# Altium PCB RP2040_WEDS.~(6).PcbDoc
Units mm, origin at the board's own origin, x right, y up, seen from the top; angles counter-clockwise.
Board outline 55 x 66 mm, 2 copper layers (F.Cu, B.Cu); 69 components, 40 nets, 258 pads, 71 vias.
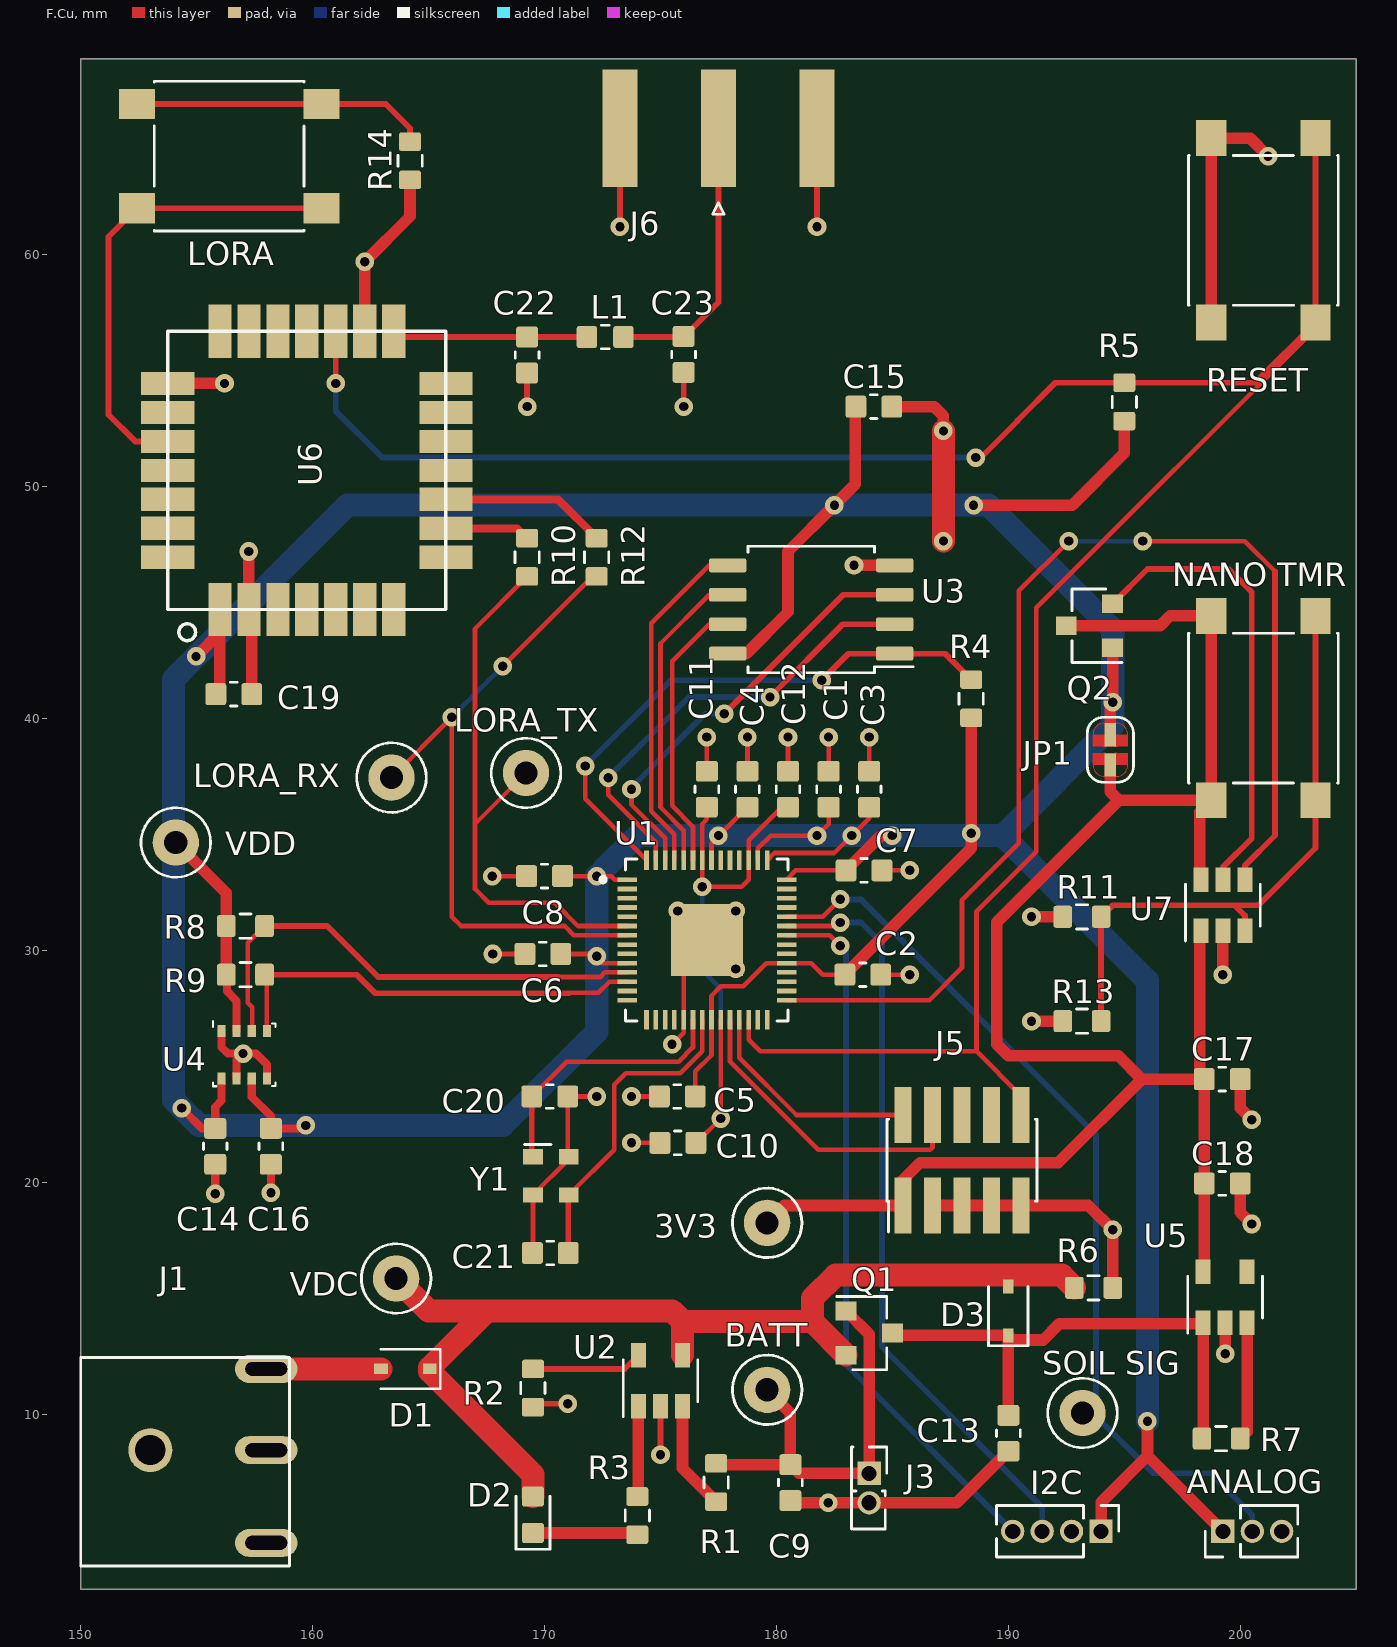
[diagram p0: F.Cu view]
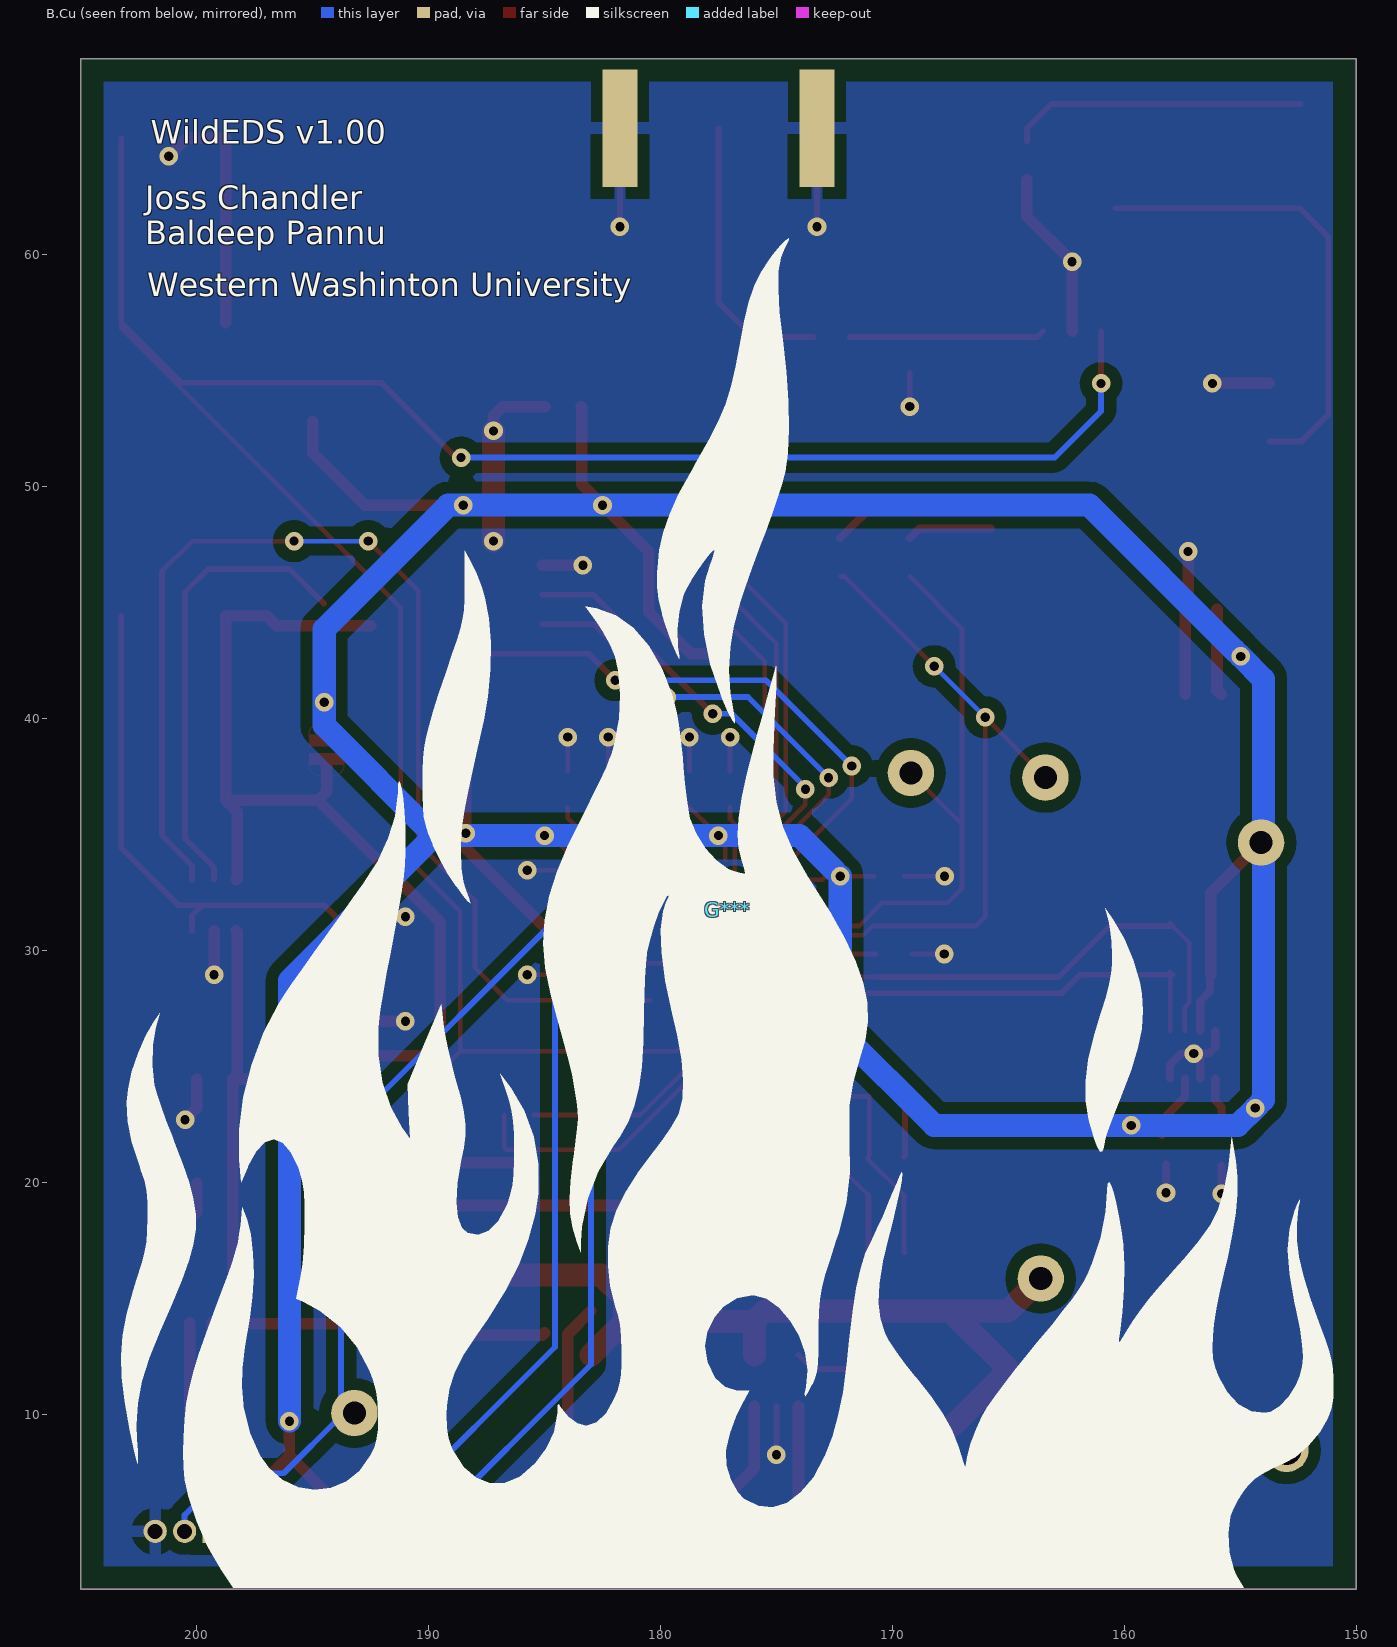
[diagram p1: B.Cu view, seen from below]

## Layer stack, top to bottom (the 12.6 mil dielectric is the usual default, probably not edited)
F.Mask: solder mask 0.0102, Solder Resist, Dk 3.5
F.Cu: signal copper 0.0356
Dielectric 1: dielectric 0.32, FR-4, Dk 4.8
B.Cu: signal copper 0.0356
B.Mask: solder mask 0.0102, Solder Resist, Dk 3.5

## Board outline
205,68.45 205,2.45 150,2.45 150,68.45 205,68.45

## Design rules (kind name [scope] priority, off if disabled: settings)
Clearance "Clearence 0.508_Polygon" [InNamedPolygon('B.Cu-GND')] p1: gap=0.508 ignorepadtopadclearanceinfootprint=FALSE
Clearance "Clearence 0.2_NetClass" [InNetClass('Default')] p2: gap=0.2 ignorepadtopadclearanceinfootprint=FALSE
HoleSize "Hole Size (Default)" [All] p1: absolutevalues=TRUE maxlimit=10 minlimit=0.3 maxpercent=80.000 minpercent=20.000
MinimumSolderMaskSliver [All] p1: minsoldermaskwidth=0
PolygonConnect Polygon_B.Cu-GND_ConnectDirect [IsNamedPolygon('B.Cu-GND') vs IsVia] p1: connectstyle=Direct reliefconductorwidth=0.254 reliefentries=4 polygonreliefangle="90 Angle" airgapwidth=0.254
PolygonConnect Polygon_B.Cu-GND_ConnectRelief45 [IsNamedPolygon('B.Cu-GND') vs (IsThruPin or IsSMTPin) and (PadShape_AllLayers = 'Round')] p2: connectstyle=Relief reliefconductorwidth=0.508 reliefentries=4 polygonreliefangle="45 Angle" airgapwidth=0.508
PolygonConnect Polygon_B.Cu-GND_ConnectRelief90 [IsNamedPolygon('B.Cu-GND') vs (IsThruPin or IsSMTPin) and (PadShape_AllLayers <> 'Round')] p3: connectstyle=Relief reliefconductorwidth=0.508 reliefentries=4 polygonreliefangle="90 Angle" airgapwidth=0.508
RoutingVias [All] p1: holewidth=0.711 width=1.27 viastyle="Through Hole" minholewidth=0.711 minwidth=1.27 maxholewidth=0.711 maxwidth=1.27
SilkToSilkClearance [All] p1: silktosilkclearance=0
SilkToSolderMaskClearance [IsPad] p1: minsilkscreentomaskgap=0 clearancetoexposedcopper=TRUE
SolderMaskExpansion [All] p1: expansion=0.102 istentingtop=FALSE
Width [All] p1: maxlimit=10 minlimit=0.2 preferedwidth=0.25 minimp=50.000000 maximp=50.000000 favimp=50.000000
26 further rules are at their usual default settings.

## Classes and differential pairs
net class Default: +1V1 +3V3 +BATT DONE GND LORA_RX LORA_TX Net-(C13-Pad1) Net-(C22-Pad1) Net-(C23-Pad1) Net-(D1-Pad2) Net-(D2-Pad1) Net-(Q2-Pad2) Net-(R1-Pad2) Net-(R2-Pad2) Net-(R3-Pad2) Net-(R7-Pad1) Net-(R10-Pad1) Net-(R11-Pad2) Net-(R12-Pad1) Net-(R14-Pad2) Net-(SW3-Pad1) QSPI_CLK QSPI_CSN QSPI_SD0 QSPI_SD1 QSPI_SD2 QSPI_SD3 RESET SCL SCL_SOIL SDA SDA_SOIL SOIL_SIG SWD_CLK SWD_DIO VDC VDD XIN XOUT

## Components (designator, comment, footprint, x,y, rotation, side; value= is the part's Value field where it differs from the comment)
3V3 "TestPoint" TestPoint_Loop_D1.80mm_Drill1.0mm_Beaded 179.6,18.25 r0 top
ANALOG "Conn_01x03_Male" PinHeader_1x03_P1.27mm_Vertical 199.25,4.95 r90 top
BATT "TestPoint" TestPoint_Loop_D1.80mm_Drill1.0mm_Beaded 179.6,11.05 r0 top
C1 "1uF" C_0603_1608Metric 182.25,36.95 r90 top
C2 "100nF" C_0603_1608Metric 183.725,28.95 r0 top
C3 "100nF" C_0603_1608Metric 184,36.95 r90 top
C4 "100nF" C_0603_1608Metric 178.75,36.95 r90 top
C5 "100nF" C_0603_1608Metric 175.725,23.7 r180 top
C6 "100nF" C_0603_1608Metric 169.926,29.845 r180 top
C7 "100nF" C_0603_1608Metric 183.775,33.45 r0 top
C8 "100nF" C_0603_1608Metric 170,33.2 r180 top
C9 "10uF" C_0603_1608Metric 180.6,7.05 r270 top
C10 "100nF" C_0603_1608Metric 175.75,21.7 r180 top
C11 "100nF" C_0603_1608Metric 177,36.95 r90 top
C12 "1uF" C_0603_1608Metric 180.5,36.95 r90 top
C13 "10uF" C_0603_1608Metric 190,9.175 r270 top
C14 "100nF" C_0603_1608Metric 155.8,21.55 r270 top
C15 "C" C_0603_1608Metric 184.2,53.45 r0 top
C16 "100nF" C_0603_1608Metric 158.2,21.55 r270 top
C17 "10uF" C_0603_1608Metric 199.225,24.45 r0 top
C18 "10uF" C_0603_1608Metric 199.225,19.95 r0 top
C19 "4.7uF" C_0603_1608Metric 156.6,41.05 r0 top
C20 "8pF" C_0603_1608Metric 170.225,23.7 r0 top
C21 "8pF" C_0603_1608Metric 170.25,16.95 r0 top
C22 "DNP" C_0603_1608Metric 169.25,55.675 r270 top
C23 "DNP" C_0603_1608Metric 176,55.7 r270 top
D1 "D_Schottky" D_SOD-323 164,11.95 r180 top
D2 "LED" LED_0603_1608Metric 169.5,5.663 r90 top
D3 "D_Schottky" D_SOD-323 190,14.45 r90 top
G*** "LOGO" Flame_Logo 177.1,31.75 r0 bottom
I2C "Conn_01x04_Male" PinHeader_1x04_P1.27mm_Vertical 194,4.95 r270 top
J1 "Barrel_Jack_Switch_Pin3Ring" 54-00125 154,13.45 r0 top
J3 "LiPo Batt" PinHeader_2x01_P1.27mm_Vertical 184,7.45 r270 top
J5 "Conn_02x05_Odd_Even" PinHeader_2x05_P1.27mm_Vertical_SMD 188,20.95 r90 top
J6 "SMA-J-P-H-RA-TH1" SMA_Amphenol_132289_EdgeMount_new 177.5,65.45 r90 top
JP1 "SolderJumper_2_Open" SolderJumper-2_P1.3mm_Open_RoundedPad1.0x1.5mm 194.4,38.65 r90 top
L1 "0H" L_0603_1608Metric 172.612,56.45 r0 top
LORA "SW_Push" SW_Push_1P1T_NO_6x6mm_H9.5mm 156.4,64.25 r180 top
LORA_RX "TestPoint" TestPoint_Loop_D1.80mm_Drill1.0mm_Beaded 163.4,37.45 r0 top
LORA_TX "TestPoint" TestPoint_Loop_D1.80mm_Drill1.0mm_Beaded 169.2,37.65 r0 top
"NANO TMR" "SW_Push" SW_Push_1P1T_NO_6x6mm_H9.5mm 201,40.45 r270 top
Q1 "Q_PMOS_DGS" SOT-23 184,13.5 r0 top
Q2 "Q_PMOS_DGS" SOT-23 193.5,44 r180 top
R1 "0" R_0603_1608Metric 177.4,7.05 r270 top
R2 "2k" R_0603_1608Metric 169.5,11.125 r90 top
R3 "10k" R_0603_1608Metric 174,5.625 r90 top
R4 "10k" R_0603_1608Metric 188.4,40.85 r270 top
R5 "10k" R_0603_1608Metric 195,53.65 r90 top
R6 "10k" R_0603_1608Metric 193.675,15.45 r0 top
R7 "10k" R_0603_1608Metric 199.175,8.95 r180 top
R8 "10k" R_0603_1608Metric 157.1,31.05 r0 top
R9 "10k" R_0603_1608Metric 157.1,28.95 r0 top
R10 "22" R_0603_1608Metric 169.25,46.95 r270 top
R11 "221k" R_0603_1608Metric 193.175,31.45 r0 top
R12 "22" R_0603_1608Metric 172.25,46.95 r270 top
R13 "287k" R_0603_1608Metric 193.175,26.95 r0 top
R14 "470" R_0603_1608Metric 164.2,64.05 r90 top
RESET "SW_Push" SW_Push_1P1T_NO_6x6mm_H9.5mm 201,61.05 r270 top
"SOIL SIG" "TestPoint" TestPoint_Loop_D1.80mm_Drill1.0mm_Beaded 193.2,10.05 r0 top
U1 "RP2040" QFN40P700X700X90-57N 177,30.45 r0 top
U2 "MCP73831-2-OT" SOT-23-5 175,11.45 r90 top
U3 "W25Q128JVS" SOIC-8_5.23x5.23mm_P1.27mm 181.5,44.7 r180 top
U4 "BME280" Bosch_LGA-8_2.5x2.5mm_P0.65mm_ClockwisePinNumbering 157.05,25.5 r0 top
U5 "AP2112K-3.3" SOT-23-5 199.35,15.05 r90 top
U6 "LoRa-E5" LoRa-E5 159.75,50.7 r90 top
U7 "TPL5110" SOT-23-6 199.25,31.95 r90 top
VDC "TestPoint" TestPoint_Loop_D1.80mm_Drill1.0mm_Beaded 163.6,15.85 r0 top
VDD "TestPoint" TestPoint_Loop_D1.80mm_Drill1.0mm_Beaded 154.1,34.65 r0 top
Y1 "Crystal_GND24" Oscillator_SMD_Abracon_ASDMB-4Pin_2.5x2.0mm 170.275,20.275 r270 top

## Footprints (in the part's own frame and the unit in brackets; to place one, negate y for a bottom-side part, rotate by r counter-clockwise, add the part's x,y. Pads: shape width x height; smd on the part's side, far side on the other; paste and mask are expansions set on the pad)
54-00125 [mm]
  rrect100% 2.7x1.2 hole 0.6 slot 1.8 at 0 deg paste-2.7 mask+0.051: 1(4,-1.5) 2(4,-5) 3(4,-9)
  round 1.9 hole 1.3 paste-1.9 mask+0.051: Un1(-1,-5)
  silkscreen extent -4,-10 5,-1
Bosch_LGA-8_2.5x2.5mm_P0.65mm_ClockwisePinNumbering [mm]
  rect 0.35x0.5 smd mask+0.051: 1(-0.975,1.025) 2(-0.325,1.025) 3(0.325,1.025) 4(0.975,1.025) 5(0.975,-1.025) 6(0.325,-1.025) 7(-0.325,-1.025) 8(-0.975,-1.025)
  silkscreen extent -1.35,-1.36 1.35,1.45
C_0603_1608Metric [mm]
  rrect25% 0.9x0.95 smd mask+0.051: 1(-0.775,0) 2(0.775,0)
  silkscreen extent -0.14,-0.51 0.14,0.51
D_SOD-323 [mm]
  rect 0.6x0.45 smd mask+0.051: 1(-1.05,0) 2(1.05,0)
  silkscreen extent -1.5,-0.85 1.05,0.85
Flame_Logo [mm]
  silkscreen extent -26.12,-28.96 26.16,29.24
L_0603_1608Metric [mm]
  rrect25% 0.875x0.95 smd mask+0.051: 1(-0.787,0) 2(0.787,0)
  silkscreen extent -0.16,-0.51 0.16,0.51
LED_0603_1608Metric [mm]
  rrect25% 0.875x0.95 smd mask+0.051: 1(-0.787,0) 2(0.787,0)
  silkscreen extent -1.49,-0.73 0.8,0.73
LoRa-E5 [mm]
  rect 2.3x1 smd mask+0.051: 1(-6,3.75) 2(-6,2.5) 3(-6,1.25) 4(-6,0) 5(-6,-1.25) 6(-6,-2.5) 7(-6,-3.75) 15(6,-3.75) 16(6,-2.5) 17(6,-1.25) 18(6,0) 19(6,1.25) 20(6,2.5) 21(6,3.75)
  rect 1x2.3 smd mask+0.051: 8(-3.75,-6) 9(-2.5,-6) 10(-1.25,-6) 11(0,-6) 12(1.25,-6) 13(2.5,-6) 14(3.75,-6) 22(3.75,6) 23(2.5,6) 24(1.25,6) 25(0,6) 26(-1.25,6) 27(-2.5,6) 28(-3.75,6)
  silkscreen extent -7.34,-6 6,6
Oscillator_SMD_Abracon_ASDMB-4Pin_2.5x2.0mm [mm]
  rect 0.65x0.85 smd mask+0.051: 1(-0.825,-0.775) 2(0.825,-0.775) 3(0.825,0.775) 4(-0.825,0.775)
  silkscreen extent -1.35,-1.14 -1.35,0
PinHeader_1x03_P1.27mm_Vertical [mm]
  rect 1x1 hole 0.65 paste-1 mask+0.051: 1(0,0)
  rrect100% 1x1 hole 0.65 paste-1 mask+0.051: 2(0,-1.27) 3(0,-2.54)
  silkscreen extent -1.11,-3.23 1.11,0.76
PinHeader_1x04_P1.27mm_Vertical [mm]
  rect 1x1 hole 0.65 paste-1 mask+0.051: 1(0,0)
  rrect100% 1x1 hole 0.65 paste-1 mask+0.051: 2(0,-1.27) 3(0,-2.54) 4(0,-3.81)
  silkscreen extent -1.11,-4.5 1.11,0.76
PinHeader_2x01_P1.27mm_Vertical [mm]
  rect 1x1 hole 0.65 paste-1 mask+0.051: 1(0,0)
  rrect100% 1x1 hole 0.65 paste-1 mask+0.051: 2(1.27,0)
  silkscreen extent -1.13,-0.76 2.4,0.76
PinHeader_2x05_P1.27mm_Vertical_SMD [mm]
  rect 2.4x0.74 smd mask+0.051: 1(-1.95,2.54) 2(1.95,2.54) 3(-1.95,1.27) 4(1.95,1.27) 5(-1.95,0) 6(1.95,0) 7(-1.95,-1.27) 8(1.95,-1.27) 9(-1.95,-2.54) 10(1.95,-2.54)
  silkscreen extent -3.09,-3.23 1.77,3.23
QFN40P700X700X90-57N [mm]
  rrect3% 0.84x0.2 smd mask+0.051: 1(-3.435,2.6) 2(-3.435,2.2) 3(-3.435,1.8) 4(-3.435,1.4) 5(-3.435,1) 6(-3.435,0.6) 7(-3.435,0.2) 8(-3.435,-0.2) 9(-3.435,-0.6) 10(-3.435,-1) 11(-3.435,-1.4) 12(-3.435,-1.8) 13(-3.435,-2.2) 14(-3.435,-2.6) 29(3.435,-2.6) 30(3.435,-2.2) 31(3.435,-1.8) 32(3.435,-1.4) 33(3.435,-1) 34(3.435,-0.6) 35(3.435,-0.2) 36(3.435,0.2) 37(3.435,0.6) 38(3.435,1) 39(3.435,1.4) 40(3.435,1.8) 41(3.435,2.2) 42(3.435,2.6)
  rrect10% 0.2x0.84 smd mask+0.051: 15(-2.6,-3.435) 16(-2.2,-3.435) 17(-1.8,-3.435) 18(-1.4,-3.435) 19(-1,-3.435) 20(-0.6,-3.435) 21(-0.2,-3.435) 22(0.2,-3.435) 23(0.6,-3.435) 24(1,-3.435) 25(1.4,-3.435) 26(1.8,-3.435) 27(2.2,-3.435) 28(2.6,-3.435) 43(2.6,3.435) 44(2.2,3.435) 45(1.8,3.435) 46(1.4,3.435) 47(1,3.435) 48(0.6,3.435) 49(0.2,3.435) 50(-0.2,3.435) 51(-0.6,3.435) 52(-1,3.435) 53(-1.4,3.435) 54(-1.8,3.435) 55(-2.2,3.435) 56(-2.6,3.435)
  rect 3.1x3.1 smd paste-3.1 mask+0.051: 57(0,0)
  silkscreen extent -4.57,-3.5 3.5,3.5
R_0603_1608Metric [mm]
  rrect25% 0.8x0.95 smd mask+0.051: 1(-0.825,0) 2(0.825,0)
  silkscreen extent -0.24,-0.52 0.24,0.52
SMA_Amphenol_132289_EdgeMount_new [mm]
  rect 5.08x1.5 smd mask+0.051: 1(0,0) 2(0,-4.25) 3(0,4.25)
  rect 5.08x1.5 smd far side mask+0.051: 4(0,4.25) 5(0,-4.25)
  silkscreen extent -3.71,-0.25 -3.21,0.25
SOIC-8_5.23x5.23mm_P1.27mm [mm]
  rrect25% 1.6x0.6 smd mask+0.051: 1(-3.6,1.905) 2(-3.6,0.635) 3(-3.6,-0.635) 4(-3.6,-1.905) 5(3.6,-1.905) 6(3.6,-0.635) 7(3.6,0.635) 8(3.6,1.905)
  silkscreen extent -4.4,-2.73 2.73,2.73
SolderJumper-2_P1.3mm_Open_RoundedPad1.0x1.5mm [mm]
  rect 1x0.5 smd paste-1 mask+0.051: 1(-0.65,0) 2(0.65,0)
  F.Cu circle w0: c-0.65,0.25 r0.5
  F.Cu circle w0: c-0.65,-0.25 r0.5
  F.Cu region: -0.15,-0.75 -0.65,-0.75 -0.65,0.75 -0.15,0.75
  F.Cu region: 0.65,-0.75 0.15,-0.75 0.15,0.75 0.65,0.75
  F.Cu lines w0: 0.217,0 ccw(c0.65,-0.25) 0.65,-0.75 ccw(c0.65,-0.25) 1.083,0 ; 0.217,0 cw(c0.65,-0.25) 1.083,0 ; 0.217,0 ccw(c0.65,0.25) 0.65,-0.25 ccw(c0.65,0.25) 1.083,0 ; 0.217,0 cw(c0.65,0.25) 1.083,0
  silkscreen extent -1.4,-1 1.4,1
SOT-23 [mm]
  rect 0.9x0.8 smd mask+0.051: 1(-1,0.95) 2(-1,-0.95) 3(1,0)
  silkscreen extent -1.4,-1.58 0.76,1.58
SOT-23-5 [mm]
  rect 1.06x0.65 smd mask+0.051: 1(-1.1,0.95) 2(-1.1,0) 3(-1.1,-0.95) 4(1.1,-0.95) 5(1.1,0.95)
  silkscreen extent -1.55,-1.61 0.9,1.61
SOT-23-6 [mm]
  rect 1.06x0.65 smd mask+0.051: 1(-1.1,0.95) 2(-1.1,0) 3(-1.1,-0.95) 4(1.1,-0.95) 5(1.1,0) 6(1.1,0.95)
  silkscreen extent -1.55,-1.61 0.9,1.61
SW_Push_1P1T_NO_6x6mm_H9.5mm [mm]
  rect 1.55x1.3 smd mask+0.051: 1(-3.975,2.25) 1(3.975,2.25) 2(-3.975,-2.25) 2(3.975,-2.25)
  silkscreen extent -3.23,-3.23 3.23,3.23
TestPoint_Loop_D1.80mm_Drill1.0mm_Beaded [mm]
  round 2 hole 1 paste-2 mask+0.051: 1(0,0)
  silkscreen extent -1.5,-1.5 1.5,1.5

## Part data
3V3 BATT LORA_RX LORA_TX "SOIL SIG" VDC VDD: library part TestPoint_Loop_D1.80mm_Drill1.0mm_Beaded, "wire loop with bead as test point, loop diameter 1.8mm, hole diameter 1.0mm"
ANALOG: library part PinHeader_1x03_P1.27mm_Vertical, "Through hole straight pin header, 1x03, 1.27mm pitch, single row"
C1 C2 C3 C4 C5 C6 C7 C8 C9 C10 C11 C12 C13 C14 C15 C16 C17 C18 C19 C20 C21 C22 C23: library part C_0603_1608Metric, "Capacitor SMD 0603 (1608 Metric), square (rectangular) end terminal, IPC_7351 nominal, (Body size source: IPC-SM-782 page 76, https://www.pcb-3d.com/wordpress/wp-content/uploads/ipc-sm-782a_amendment_1_and_2.pdf), generated with kicad-footprint-generator"
D1 D3: library part D_SOD-323, "SOD-323"
D2: library part LED_0603_1608Metric, "LED SMD 0603 (1608 Metric), square (rectangular) end terminal, IPC_7351 nominal, (Body size source: http://www.tortai-tech.com/upload/download/2011102023233369053.pdf), generated with kicad-footprint-generator"
G***: library part Flame_Logo
I2C: library part PinHeader_1x04_P1.27mm_Vertical, "Through hole straight pin header, 1x04, 1.27mm pitch, single row"
J1: library part 54-00125
J3: library part PinHeader_2x01_P1.27mm_Vertical, "Through hole straight pin header, 2x01, 1.27mm pitch, double rows"
J5: library part PinHeader_2x05_P1.27mm_Vertical_SMD, "surface-mounted straight pin header, 2x05, 1.27mm pitch, double rows"
J6: library part SMA_Amphenol_132289_EdgeMount_new, "http://www.amphenolrf.com/132289.html"
JP1: library part SolderJumper-2_P1.3mm_Open_RoundedPad1.0x1.5mm, "SMD Solder Jumper, 1x1.5mm, rounded Pads, 0.3mm gap, open"
L1: library part L_0603_1608Metric, "Inductor SMD 0603 (1608 Metric), square (rectangular) end terminal, IPC_7351 nominal, (Body size source: http://www.tortai-tech.com/upload/download/2011102023233369053.pdf), generated with kicad-footprint-generator"
LORA "NANO TMR" RESET: library part SW_Push_1P1T_NO_6x6mm_H9.5mm, "tactile push button, 6x6mm e.g. PTS645xx series, height=9.5mm"
Q1 Q2: library part SOT-23, "SOT-23, Standard"
R1 R2 R3 R4 R5 R6 R7 R8 R9 R10 R11 R12 R13 R14: library part R_0603_1608Metric, "Resistor SMD 0603 (1608 Metric), square (rectangular) end terminal, IPC_7351 nominal, (Body size source: IPC-SM-782 page 72, https://www.pcb-3d.com/wordpress/wp-content/uploads/ipc-sm-782a_amendment_1_and_2.pdf), generated with kicad-footprint-generator"
U1: library part QFN40P700X700X90-57N
U2 U5: library part SOT-23-5, "5-pin SOT23 package"
U3: library part SOIC-8_5.23x5.23mm_P1.27mm, "SOIC, 8 Pin (http://www.winbond.com/resource-files/w25q32jv%20revg%2003272018%20plus.pdf#page=68), generated with kicad-footprint-generator ipc_gullwing_generator.py"
U4: library part Bosch_LGA-8_2.5x2.5mm_P0.65mm_ClockwisePinNumbering, "LGA-8"
U7: library part SOT-23-6, "6-pin SOT-23 package"
Y1: library part Oscillator_SMD_Abracon_ASDMB-4Pin_2.5x2.0mm, "Miniature Crystal Clock Oscillator Abracon ASDMB series, 2.5x2.0mm package, http://www.abracon.com/Oscillators/ASDMB.pdf"

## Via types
v1: diameter 0.8, hole 0.4, F.Cu to B.Cu, tented both sides, 71 vias

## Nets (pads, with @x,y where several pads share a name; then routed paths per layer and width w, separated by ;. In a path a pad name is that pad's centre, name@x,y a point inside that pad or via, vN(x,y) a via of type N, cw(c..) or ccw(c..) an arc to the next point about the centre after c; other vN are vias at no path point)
+1V1: C10.1 C11.1 C12.1 U1.23 U1.45 U1.50 | length 25.7
  F.Cu w0.2: C10.1@176.55,21.7 v1(177.6,22.75) U1.23 ; C11.1@177,36.2 177,35.65 176.8,35.45 U1.50 v1(176.8,32.75) 178.5,32.75 178.8,33.05 U1.45 178.8,34.75 180.225,36.175 C12.1
  B.Cu w0.2: v1(176.8,32.75) 176.8,32.65 176.8,32.55 176.8,29.15 177.6,28.35 v1(177.6,22.75)
+3V3: 3V3.1 "NANO TMR.2" C17.1 C18.1 J5.1 JP1.1 Q2.3 U5.5 U7.1 U7.6 | length 80.2
  F.Cu w0.5: 3V3.1 180.35,19 J5.1 185.46,20.11 186.2,20.85 192.15,20.85 195.75,24.45 ; Q2.3 196.55,44 196.975,44.425 198.75,44.425 198.75,36.475 ; JP1.1 194.4,36.842 194.767,36.475 ; U7.1 198.25,30.8 198.25,24.65 C17.1 ; U7.6 198.25,33.1 198.25,35.975 198.75,36.475 ; U5.5 198.45,16.2 C18.1 C17.1 ; 194.767,36.475 189.5,31.208 189.5,25.95 190,25.45 194.75,25.45 195.75,24.45 ; 194.767,36.475 198.75,36.475 ; 195.75,24.45 C17.1
+BATT: BATT.1 C9.1 J3.1 Q1.1 R1.1 | length 17.8
  F.Cu w0.5: R1.1 177.45,7.825 C9.1 ; BATT.1 180.6,10.05 C9.1 ; Q1.1 184,13.45 J3.1 180.975,7.45 C9.1
DONE: U1.29 U7.4 | length 51.7
  F.Cu w0.2: U1.29 186.6,27.85 188,29.25 188,32.164 190.45,34.614 190.45,38 190.45,45.5 v1(192.6,47.65) ; v1(195.8,47.65) 200.2,47.65 201.5,46.35
  F.Cu w0.25: U7.4 200.2,33.65 201.5,34.95 201.5,46.35
  B.Cu w0.2: v1(192.6,47.65) v1(195.8,47.65)
GND: ANALOG.3 C1.2 C2.2 C3.2 C4.2 C5.2 C6.2 C7.2 C8.2 C9.2 C10.2 C11.2 C12.2 C13.2 C14.2 C15.2 C16.2 C17.2 C18.2 C19.2 C20.2 C21.1 C22.2 C23.2 I2C.2 J1.2 J1.3 J3.2 J5.3 J5.5 J5.7 J5.9 J6.2 J6.3 J6.4 J6.5 R2.1 R6.2 R11.1 R13.1 R14.1 RESET.2 U1.19 U1.57 U2.2 U3.4 U4.1 U4.5 U4.7 U5.2 U6.2 U6.16 U6.22 U7.2 Y1.2 Y1.4 | length 118
  F.Cu w0.2: v1(167.767,29.845) C6.2 ; v1@168,33.2 C8.2 C8.2@169.5,33.2 ; C21.1 169.5,16.975 Y1.2 ; Y1.2@169.475,19.425 Y1.2 ; v1(172.25,23.7) C20.2 171,21.15 Y1.4 171.05,21 Y1.2 ; v1(173.75,21.7) C10.2 ; v1(173.75,23.7) C5.2 ; v1(175.5,25.95) 176,26.45 176,29.45 U1.57 ; C11.2 v1(177,39.2) ; C4.2 v1(178.75,39.2) ; C12.2 v1(180.5,39.2) ; C1.2 v1(182.25,39.2) ; C3.2 v1(184,39.2) ; C2.2 v1(185.75,28.95) ; C7.2 v1(185.75,33.45)
  F.Cu w0.25: v1(169.25,53.45) C22.2 ; R2.1 169.65,10.45 v1(171,10.45) ; v1(173.25,61.2) J6.3 ; v1@175,8.45 U2.2 ; v1(176,53.45) C23.2 ; v1(181.75,61.2) J6.2
  F.Cu w0.35: v1@155.8,19.75 C14.2@155.8,20.725 ; U4.1 156.075,25.825 156.35,25.55 v1(157,25.55) ; U4.7 156.725,25.275 v1(157,25.55) ; U4.5 158.025,25.075 157.55,25.55 v1(157,25.55) ; v1(158.2,19.55) C16.2
  F.Cu w0.5: U6.22 v1(156.2,54.45) ; v1(157.25,47.2) U6.2 157.375,44.575 C19.2 ; U6.16 v1(162.25,59.7) 164.2,61.65 R14.1 ; C9.2 180.695,6.18 v1(182.23,6.18) J3.2 187.78,6.18 C13.2 ; v1(183.345,46.605) U3.4 ; C15.2 186.8,53.45 187.2,53.05 v1(187.2,52.4) ; J5.3 J5.5 J5.7 J5.9 193.45,19 v1(194.5,17.95) R6.2 ; v1(191,26.95) R13.1 ; v1(191,31.45) R11.1 ; RESET.2@198.75,57.075 198.75,65.025 200.425,65.025 v1(201.2,64.25) ; v1(199.25,28.95) U7.2 ; v1(199.35,12.6) U5.2 ; C18.2 200,18.7 v1(200.5,18.2) ; C17.2 200,23.2 v1(200.5,22.7)
  F.Cu w1: v1(187.2,47.65) v1(187.2,52.4)
  other v1: 175,8.25 155.8,19.5 178.25,29.2 175.75,31.7 178.25,31.7 167.75,33.2
LORA_RX: LORA_RX.1 R12.2 U1.7 | length 29.1
  F.Cu w0.2: LORA_RX.1 v1(166,40.05) ; v1@166,40.25 v1(166,40.05) ; v1(168.2,42.25) 172.075,46.125 R12.2 ; U1.7 171.267,30.65 170.867,31.05 166.4,31.05 166,31.45 166,32.65 v1(166,40.05)
  B.Cu w0.2: v1(166,40.05) v1(168.2,42.25)
LORA_TX: LORA_TX.1 R10.2 U1.6 | length 25.3
  F.Cu w0.2: LORA_TX.1 167,35.45 167,34.85 ; R10.2 167,43.875 167,35.65 167,34.85 ; U1.6 171.433,31.05 170.433,32.05 167.6,32.05 167,32.65 167,34.85
Net-(C13-Pad1): C13.1 D3.1 Q1.3 R7.2 U5.1 | length 22.3
  F.Cu w0.5: Q1.3 185.1,13.4 D3.1 ; C13.1 D3.1 ; R7.2 198.4,9 U5.1 198.35,13.9 192.2,13.9 191.5,13.2 190.2,13.2 D3.1
Net-(C22-Pad1): C22.1 L1.1 U6.15 | length 8.4
  F.Cu w0.25: U6.15 163.75,56.45 L1.1
Net-(C23-Pad1): C23.1 J6.1 L1.2 | length 12.2
  F.Cu w0.25: L1.2 175.975,56.45 C23.1 176.025,56.475 177.5,57.95 J6.1
Net-(D1-Pad2): D1.2 J1.1 | length 5
  F.Cu w1: J1.1 D1.2
Net-(D2-Pad1): D2.1 R3.1 | length 4.5
  F.Cu w0.25: R3.1@173.925,4.875 R3.1
  F.Cu w0.5: D2.1 R3.1@173.925,4.875
Net-(Q2-Pad2): Q2.2 U7.5 | length 20
  F.Cu w0.25: Q2.2 196,46.45 199.5,46.45 200.5,45.45 200.5,34.83 199.25,33.58 U7.5
Net-(R1-Pad2): R1.2 U2.3 | length 4.7
  F.Cu w0.5: U2.3 175.95,7.675 R1.2
Net-(R2-Pad2): R2.2 U2.5 | length 4.8
  F.Cu w0.25: R2.2 173.45,11.95 U2.5
Net-(R3-Pad2): R3.2 U2.1 | length 3.9
  F.Cu w0.25: R3.2 R3.2@174.05,6.5
  F.Cu w0.5: R3.2@174.05,6.5 U2.1
Net-(R7-Pad1): R7.1 U5.3 | length 5.1
  F.Cu w0.5: R7.1 200.3,9.25 U5.3
Net-(R10-Pad1): R10.1 U6.9 | length 3.7
  F.Cu w0.35: U6.9 168.825,48.2 R10.1
Net-(R11-Pad2): "NANO TMR.1" R11.2 R13.2 U7.3 | length 26.7
  F.Cu w0.25: R13.2 194,30.95 R11.2 194.5,31.95 200.13,31.95 ; U7.3 200.2,31.5 199.75,31.95 200.13,31.95 ; 203.25,44.425 203.25,36.475 203.25,34.41 200.79,31.95 200.13,31.95
Net-(R12-Pad1): R12.1 U6.10 | length 7.2
  F.Cu w0.35: U6.10 170.575,49.45 R12.1
Net-(R14-Pad2): LORA.2 R14.2 | length 12.8
  F.Cu w0.25: LORA.2@152.425,66.5 160.375,66.5 163.15,66.5 164.2,65.45 R14.2
Net-(SW3-Pad1): LORA.1 U6.24 | length 20.4
  F.Cu w0.25: U6.24 152.35,51.95 151.2,53.1 151.2,60.775 152.425,62 LORA.1@160.375,62
QSPI_CLK: U1.52 U3.6 | length 13.5
  F.Cu w0.2: U1.52 176,35.167 175,36.167 175,43.235 177.1,45.335 U3.6
QSPI_CSN: R4.1 U1.56 U3.1 | length 24.3
  F.Cu w0.2: v1(171.75,37.95) 171.75,36.535 U1.56
  F.Cu w0.25: v1(181.95,41.65) 183.095,42.795 U3.1 187.28,42.795 R4.1
  B.Cu w0.25: v1(171.75,37.95) 175.45,41.65 v1(181.95,41.65)
QSPI_SD0: U1.53 U3.5 | length 15
  F.Cu w0.2: U1.53 175.6,35.001 174.6,36.001 174.6,44.105 177.1,46.605 U3.5
QSPI_SD1: U1.55 U3.2 | length 19.5
  F.Cu w0.2: v1(172.75,37.45) 172.75,36.72 174.8,34.67 U1.55
  F.Cu w0.25: v1(179.725,40.925) 182.865,44.065 U3.2
  B.Cu w0.25: v1(172.75,37.45) 176.225,40.925 179.475,40.925 v1(179.725,40.925)
QSPI_SD2: U1.54 U3.3 | length 18.5
  F.Cu w0.2: v1(173.75,36.95) 173.75,36.286 175.2,34.836 U1.54
  F.Cu w0.25: v1(177.75,40.2) 182.885,45.335 U3.3
  B.Cu w0.25: v1(173.75,36.95) 173.75,37.023 176.927,40.2 v1(177.75,40.2)
QSPI_SD3: U1.51 U3.7 | length 12
  F.Cu w0.2: U1.51 176.4,35.333 175.5,36.233 175.5,42.465 177.1,44.065 U3.7
RESET: J5.10 R5.2 RESET.1 U1.26 U6.17 | length 109.7
  F.Cu w0.2: U1.26 178.8,26.15 179.3,25.65 188.63,25.65 ; J5.10 190.54,23.74 188.63,25.65 ; RESET.1@203.25,57.075 203.25,56.819 191.2,44.769 191.2,34.25 188.63,31.68 188.63,25.65
  F.Cu w0.25: v1(161,54.45) U6.17 ; v1(188.6,51.25) 188.825,51.25 190.4,52.825 190.4,52.85 192.025,54.475 R5.2 200.65,54.475 203.25,57.075 RESET.1@203.25,65.025 ; J5.10 J5.10@190.54,23.73
  B.Cu w0.25: v1(161,54.45) 161,53.25 163,51.25 v1(188.6,51.25)
SCL: R9.2 U1.12 U4.4 | length 18.8
  F.Cu w0.2: R9.2 158.025,28.85 U4.4 ; 171.033,28.167 172.317,28.167 172.8,28.65 U1.12
  F.Cu w0.25: R9.2@158.025,29.05 R9.2 161.9,28.95 162.701,28.149 170.899,28.149 171.051,28.149
SCL_SOIL: I2C.3 U1.37 | length 32.8
  F.Cu w0.2: U1.37 182.6,31.05 v1(182.75,31.2)
  B.Cu w0.25: v1(182.75,31.2) 183.65,31.2 184.55,30.3 184.55,12.9 191.46,5.99 I2C.3
SDA: R8.2 U1.11 U4.3 | length 21.7
  F.Cu w0.2: U4.3 157.4,26.55 157.4,27.55 157.2,27.75 157.2,30.325 R8.2 ; 170.6,28.85 172.4,28.85 172.6,29.05 U1.11
  F.Cu w0.25: R8.2@158.025,31.15 R8.2 160.625,31.05 162.825,28.85 170.6,28.85
SDA_SOIL: I2C.4 U1.36 | length 30.8
  F.Cu w0.2: U1.36 182.3,30.65 v1(182.75,30.2)
  B.Cu w0.25: v1(182.75,30.2) 183,29.95 183,12.14 I2C.4
SOIL_SIG: "SOIL SIG.1" ANALOG.2 U1.38 | length 39.2
  F.Cu w0.2: U1.38 182,31.45 v1(182.75,32.2)
  B.Cu w0.25: v1(182.75,32.2) 183.636,32.2 193.775,22.061 193.775,9.925 196.25,7.45 198.727,7.45 200.52,5.657 ANALOG.2
SWD_CLK: J5.4 U1.24 | length 13.6
  F.Cu w0.2: U1.24 178,25.2 181.8,21.4 186.63,21.4 186.73,21.5 J5.4
SWD_DIO: J5.2 U1.25 | length 9.7
  F.Cu w0.2: U1.25 178.4,25.366 180.866,22.9 181.866,22.9 J5.2
VDC: D1.1 D2.2 D3.2 Q1.2 R6.1 U2.4 VDC.1 | length 46
  F.Cu w1: VDC.1 165,14.45 167.5,14.45 ; D2.2 169.5,7.4 165.05,11.85 D1.1 165.05,12 167.5,14.45 ; U2.4 175.95,14 ; Q1.2 181.55,14 ; R6.1 192.3,16 182.55,16 181.55,15 181.55,14 ; 167.5,14.45 175.5,14.45 175.95,14 ; 175.95,14 180.05,14 181.55,14
VDD: ANALOG.1 C1.1 C2.1 C3.1 C4.1 C5.1 C6.1 C7.1 C8.1 C14.1 C15.1 C16.1 C19.1 I2C.1 JP1.2 Q2.1 R4.2 R5.1 R8.1 R9.1 U1.1 U1.10 U1.22 U1.33 U1.42 U1.43 U1.44 U1.49 U3.8 U4.2 U4.6 U4.8 U6.1 VDD.1 | length 255.7
  F.Cu w0.2: C6.1 172.105,29.845 172.225,29.725 172.5,29.45 U1.10 ; C8.1 v1(172.25,33.2) 172.874,33.2 173.024,33.05 U1.1 ; C5.1 176.5,24.783 177.2,25.483 177.2,28.05 177.6,28.45 178.564,28.45 179.564,29.45 U1.33 181.5,29.45 182,28.95 C2.1 ; U1.49 177.2,34.625 177.512,34.938 177.775,35.2 C4.1 ; U1.44 179.2,34.4 179.75,34.95 v1(181.75,34.95) 182.25,35.45 C1.1 ; U1.43 179.915,34.2 182.5,34.2 v1(183.25,34.95) 184,35.7 C3.1 ; U1.42 180.835,33.45 C7.1
  F.Cu w0.35: v1@154.4,23.15 155.225,22.325 C14.1 155.8,23.25 156.075,23.525 U4.8 ; R9.1 156.3,28.925 156.3,28.25 156.725,27.825 U4.2 ; U4.6 157.375,23.675 158.2,22.85 C16.1 159.575,22.325 v1(159.7,22.45) ; C16.1@158.1,22.325 158.15,22.275 C16.1@158.375,22.05
  F.Cu w0.5: VDD.1 156.275,32.475 R8.1 R9.1 ; v1(154.975,42.675) U6.1@156,43.7 ; C19.1 156,41.225 U6.1@156,43.7 ; U6.1 U6.1@156,43.7 ; U3.8 178.7,42.795 180.5,44.595 180.5,47.2 v1(182.5,49.2) 183.4,50.1 183.4,53.425 C15.1 ; C2.1 188.4,34.4 v1(188.4,35.05) R4.2 ; C7.1 184.5,34.95 v1(185,34.95) ; v1(188.5,49.2) 192.75,49.2 195,51.45 R5.1 ; I2C.1 194,6.2 196,8.2 ; JP1.2 194.4,39.733 194.4,40.6 v1(194.5,40.7) Q2.1 ; v1(196,9.7) 196,8.2 ; ANALOG.1 196,8.2
  B.Cu w1: v1(172.25,33.2) v1(172.25,29.75) 172.25,29.45 172.25,26.5 168.2,22.45 v1(159.7,22.45) 155.1,22.45 v1(154.35,23.2) 154,23.55 154,41.7 v1(154.975,42.675) 155.25,42.95 161.5,49.2 v1(182.5,49.2) v1(188.5,49.2) 189.15,49.2 194.5,43.85 v1(194.5,40.7) 194.5,39.7 189.75,34.95 ; v1@172.5,33.45 174,34.95 v1(177.5,34.95) v1(181.75,34.95) v1(183.25,34.95) v1(185,34.95) 189.75,34.95 ; v1(196,9.7) 196,28.7 189.75,34.95
XIN: C20.1 U1.20 Y1.1 | length 11.8
  F.Cu w0.2: C20.1 170.95,25.2 175.786,25.2 176.4,25.814 U1.20 ; C20.1@169.7,23.7 C20.1@169.7,23.9
  F.Cu w0.25: C20.1 169.45,21.15 Y1.1
XOUT: C21.2 U1.21 Y1.3 | length 13.8
  F.Cu w0.2: Y1.3 173,21.4 173,24.2 173.5,24.7 175.852,24.7 176.8,25.648 U1.21
  F.Cu w0.25: C21.2 171.025,19.425 Y1.3
pads on no net: J1.Un1 J5.6 J5.8 U1.2 U1.3 U1.4 U1.5 U1.8 U1.9 U1.13 U1.14 U1.15 U1.16 U1.17 U1.18 U1.27 U1.28 U1.30 U1.31 U1.32 U1.34 U1.35 U1.39 U1.40 U1.41 U1.46 U1.47 U1.48 U5.4 U6.3 U6.4 U6.5 U6.6 U6.7 U6.8 U6.11 U6.12 U6.13 U6.14 U6.18 U6.19 U6.20 U6.21 U6.23 U6.25 U6.26 U6.27 U6.28

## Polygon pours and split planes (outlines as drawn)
GND on B.Cu "B.Cu-GND" (solid, remove dead copper, pour order 0): 204,3.45 151,3.45 151,67.45 204,67.45

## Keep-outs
Edge.Cuts:
  lines w0.05: 150,2.45 150,68.45 ; 150,2.45 205,2.45 ; 150,2.45 150,68.45 ; 150,2.45 205,2.45 ; 150,68.45 205,68.45 ; 150,68.45 205,68.45 ; 205,2.45 205,68.45 ; 205,2.45 205,68.45

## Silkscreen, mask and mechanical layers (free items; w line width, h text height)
B.SilkS:
  text "WildEDS v1.00" at 201.978,64.776 h1
  text "Joss Chandler / Baldeep Pannu" at 202.22,60.454 h1
  text "Western Washinton University" at 202.122,58.21 h1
